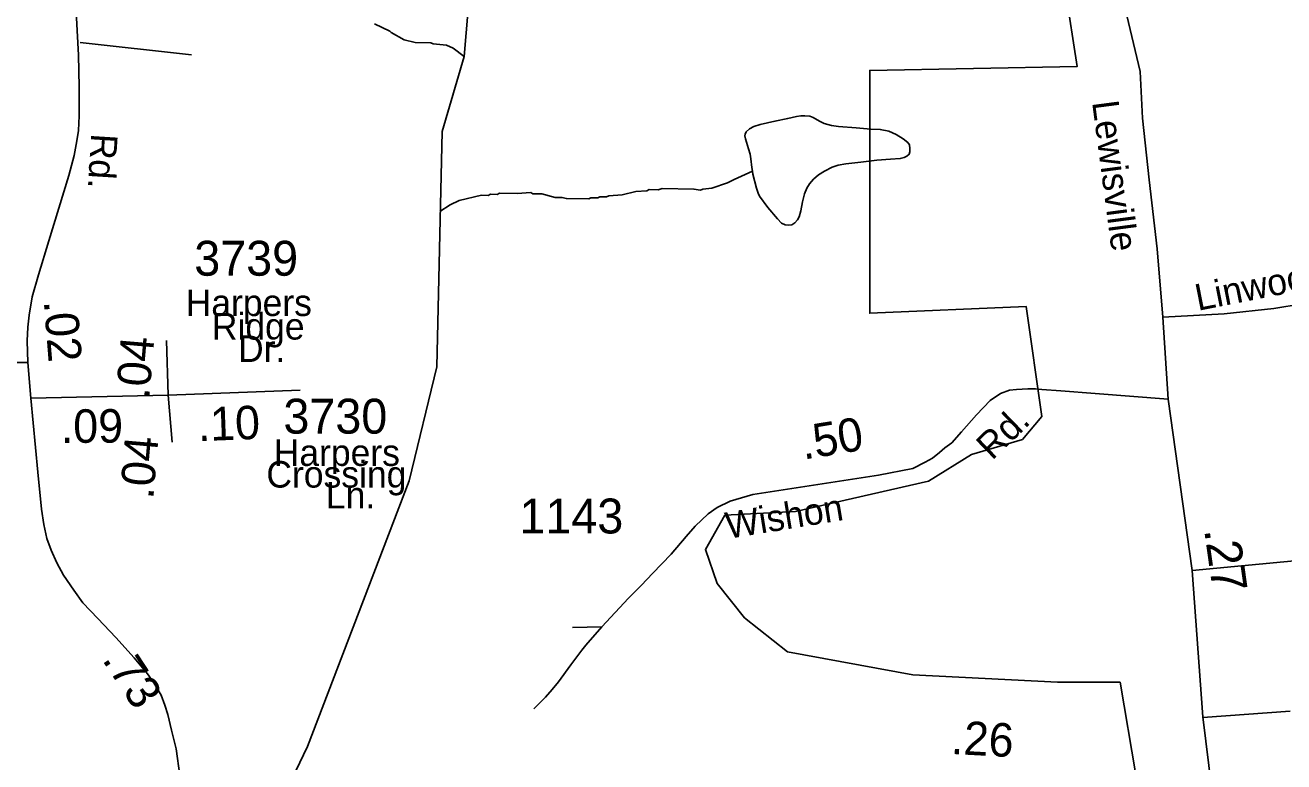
# Model space of a CAD drawing. Extents: x 1547597 to 1699558, y 810033 to 920809.
# Drawn here: x 1585386 to 1589892, y 839713 to 842351 of the extents above; entities that cross this region are included whole.
import ezdxf

# ---------------------------------------------------------------- set-up
doc = ezdxf.new("R2010")
doc.units = 0
for name, color, linetype in [('Exist Boundary Political City Limit New', 7, 'Continuous'), ('Exist Hydrographic Creek Single Shore', 7, 'Continuous'), ('Exist Hydrographic Misc Water Feature', 7, 'Continuous'), ('Exist Road Non-System Type 51', 7, 'Continuous'), ('Exist Road Non-System Type 51 Label', 7, 'Continuous'), ('Exist Road Secondary Mileage Hundredths English Label', 7, 'Continuous'), ('Exist Road Secondary Type 51 Attributed', 7, 'Continuous'), ('Exist Road Secondary Type 51 Label', 7, 'Continuous'), ('Exist Road Secondary Type 51 Number Label', 7, 'Continuous'), ('Map Preparation Boundary City Limit Buffer Line', 7, 'Continuous')]:
    doc.layers.add(name, color=color, linetype=linetype)

msp = doc.modelspace()

# ---------------------------------------------------------------- linework, layer by layer
at = {"layer": 'Exist Boundary Political City Limit New'}
msp.add_lwpolyline([(1589110.1, 842474), (1589152.2, 842202.2), (1588409.8, 842188.6), (1588409.8, 841318.7), (1588970.1, 841343), (1589026.1, 840948.8), (1588956.1, 840867.3), (1588774, 840812.9), (1588619.9, 840717.8), (1588143.6, 840609), (1587891.5, 840595.4), (1587821.5, 840473.1), (1587863.5, 840350.8), (1587961.5, 840228.5), (1588115.6, 840106.1), (1588563.9, 840024.6), (1589082.1, 839997.4), (1589306.2, 839997.4), (1589586.4, 838339.2)], dxfattribs=at)
at = {"layer": 'Exist Hydrographic Creek Single Shore'}
msp.add_lwpolyline([(1585117.5, 838293.2), (1585547.6, 838619.3), (1585792.5, 838867), (1585903.6, 839032.3), (1586217.5, 839393.6), (1586397.5, 839767.4), (1586761.5, 840718.6), (1586859.5, 841126.9), (1586879.5, 841970.2), (1586957.5, 842238.7), (1586986.8, 842579.1), (1586985.5, 842926.6), (1587021.2, 843660.8), (1587109.6, 843958.2), (1587214.6, 844349.9), (1587369.6, 844655.4), (1587407.5, 844969.8), (1587404.6, 845370.3), (1587343.5, 845755.6), (1587421.6, 845980.6), (1587450.6, 846262.3), (1587508.6, 847345.1)], dxfattribs=at)
at = {"layer": 'Exist Hydrographic Misc Water Feature'}
for points in [[(1586636.7, 842355.1), (1586691.2, 842329.2), (1586696.1, 842323.8), (1586742.7, 842298.5), (1586782.6, 842288.1), (1586838.6, 842287.4), (1586846.6, 842283.3), (1586894.5, 842278.7), (1586918.4, 842268.3), (1586957.5, 842238.7)], [(1587990, 841828.2), (1587988.3, 841840.7), (1587984.6, 841871.7), (1587981.4, 841888.4), (1587975.2, 841908.1), (1587965.1, 841943.4), (1587962.9, 841954.2), (1587963.6, 841960.7), (1587967.9, 841968.3), (1587978.8, 841978.8), (1587994.4, 841988), (1588017.1, 841994.8), (1588070.3, 842006.3), (1588116.2, 842016.8), (1588147.3, 842023.3), (1588162.7, 842025.4), (1588177.6, 842025.8), (1588195.4, 842024.8), (1588207.8, 842019.9), (1588229.6, 842006.4), (1588246.7, 841999), (1588273.4, 841991.3), (1588298.2, 841987.3), (1588361.7, 841982.6), (1588413.4, 841978.7), (1588447.2, 841977.5), (1588478.1, 841971), (1588504.7, 841959.2), (1588529.4, 841943.3), (1588545.8, 841929.9), (1588551.6, 841921.5), (1588553.8, 841908.4), (1588553.6, 841897.1), (1588550.4, 841888.2), (1588543.1, 841881.2), (1588533.6, 841876.6), (1588519.2, 841872.8), (1588484.7, 841870.4), (1588435.2, 841867.7), (1588377.5, 841859.8), (1588323.9, 841853.7), (1588297, 841849.4), (1588274.9, 841841.5), (1588247.9, 841828.3), (1588226.3, 841815), (1588208.8, 841799.3), (1588194.2, 841782.9), (1588185, 841766.4), (1588176.4, 841746.4), (1588169.3, 841717.4), (1588162.8, 841686), (1588157.1, 841664.7), (1588150.9, 841652.9), (1588141.3, 841642.4), (1588131.1, 841636), (1588119.2, 841634.4), (1588107.3, 841635.9), (1588093.6, 841641.5), (1588079.1, 841656.6), (1588044.7, 841697.6), (1588015.1, 841738.6), (1588009.9, 841748.8), (1588004.2, 841766.7), (1587991.4, 841817.5), (1587990, 841828.2)], [(1587990, 841828.2), (1587924.6, 841797.9), (1587900.5, 841786.2), (1587844.2, 841766.9), (1587812.2, 841763.4), (1587804.1, 841759.5), (1587780.2, 841763.8), (1587666.2, 841765.2), (1587652.2, 841761.4), (1587620.2, 841761.8), (1587612.2, 841757.9), (1587572.1, 841754.4), (1587524, 841743), (1587476, 841739.6), (1587467.9, 841735.7), (1587443.9, 841736), (1587435.9, 841732.1), (1587411.9, 841732.4), (1587403.8, 841728.5), (1587323.9, 841729.5), (1587308, 841733.7), (1587284, 841734), (1587236.1, 841746.6), (1587204.1, 841747), (1587196.2, 841751.1), (1587148.1, 841747.7), (1587084.2, 841748.5), (1587076.2, 841744.6), (1587052.2, 841744.9), (1587044.1, 841741), (1587020.1, 841741.3), (1586939.9, 841722.3), (1586907.7, 841706.8), (1586870.6, 841682.9)]]:
    msp.add_lwpolyline(points, dxfattribs=at)
at = {"layer": 'Exist Road Non-System Type 51'}
for p, q in [((1585583.7, 842288), (1585981.2, 842244.1)), ((1587450.4, 840195.6), (1587346.3, 840193.5)), ((1589915.1, 839894.1), (1589602.3, 839871))]:
    msp.add_line(p, q, dxfattribs=at)
for points in [[(1589459.1, 841304.4), (1589678.8, 841317.3), (1589855.9, 841335.7), (1589957.4, 841352.3), (1590075.6, 841396.6), (1590375.5, 841533.2), (1590454.8, 841566.4), (1590488.1, 841575.7), (1590548, 841581.2), (1590599.7, 841579.3), (1590704, 841568.3)], [(1589564.2, 840397.5), (1589980.9, 840437.5), (1590067, 840438.2), (1590134.9, 840435.2), (1590188.9, 840434.5), (1590221, 840435.8), (1590277.2, 840443.1), (1590301.3, 840450.8), (1590337.5, 840468.3), (1590353.8, 840480), (1590372.1, 840495.8)], [(1587295.6, 839998.9), (1587273.5, 839971.3), (1587248.9, 839944.3), (1587207.1, 839902.5)]]:
    msp.add_lwpolyline(points, dxfattribs=at)
at = {"layer": 'Exist Road Secondary Type 51 Attributed'}
for points in [[(1589477.6, 841011.9), (1589459.1, 841304.4), (1589438.8, 841549.8), (1589409.6, 841796.2), (1589386.2, 842017.1), (1589377.6, 842185.1), (1589329.6, 842385.6), (1589301.1, 842561.6), (1589283.2, 842699.3), (1589280.7, 842795.5), (1589287.7, 842850.7), (1589283, 842943.2), (1589280.1, 843015.3), (1589281.4, 843141.5), (1589298.4, 843316.5), (1589317.9, 843904.6), (1589327.5, 844094.6)], [(1585566.5, 842443.3), (1585576.8, 842243.4), (1585579.2, 842130.2), (1585579.5, 842025.8), (1585577.7, 841973.9), (1585571.2, 841936.7), (1585561.2, 841883.7), (1585543.2, 841811.7), (1585470.9, 841578.8), (1585433.8, 841456.7), (1585411.4, 841377.7), (1585400.2, 841312.2), (1585395.5, 841269.1), (1585393.7, 841220.2), (1585395.8, 841142.3)], [(1585892.2, 841221.2), (1585898.1, 841026.1)], [(1585352.1, 841142.3), (1585395.8, 841142.3)], [(1585395.8, 841142.3), (1585407, 841014.4)], [(1585407, 841014.4), (1585898.1, 841026.1)], [(1585898.1, 841026.1), (1586370.8, 841043.8)], [(1585898.1, 841026.1), (1585912.9, 840857.6)], [(1589477.6, 841011.9), (1589217.1, 841031.5), (1589094.3, 841041.4), (1589025.5, 841046.3), (1589003.4, 841048.7), (1588976.3, 841048.7), (1588934.6, 841046.3), (1588910, 841043.8), (1588878, 841031.5), (1588841.2, 841006.9), (1588792, 840955.3), (1588738, 840893.8), (1588703.6, 840854.5), (1588679, 840837.3), (1588659.3, 840820.1), (1588634.8, 840800.4), (1588607.7, 840785.6), (1588563.5, 840763.5), (1588440.6, 840738.9), (1587991, 840670.1), (1587909.9, 840645.5), (1587863.2, 840623.4), (1587831.3, 840601.2), (1587784.6, 840557), (1587752.6, 840520.1), (1587698.6, 840456.2), (1587632.2, 840387.3), (1587592.9, 840345.5), (1587546.2, 840298.8), (1587450.4, 840195.6), (1587393.2, 840130.7), (1587379.1, 840112), (1587339.8, 840060.3), (1587295.6, 839998.9)], [(1585407, 841014.4), (1585431.7, 840750.1), (1585444.4, 840618), (1585452.7, 840562.6), (1585463.3, 840512.5), (1585479.8, 840470.6), (1585499.3, 840425.2), (1585523.7, 840381), (1585560.9, 840327.9), (1585593.3, 840282.5), (1585647, 840226.4), (1585710.4, 840157.4), (1585777, 840084.9), (1585824.2, 840028.3), (1585846.6, 839995.8), (1585872.6, 839951.6), (1585886.1, 839915), (1585897.6, 839882.6), (1585910.6, 839826), (1585926.5, 839759.3), (1585939.5, 839663.8)], [(1589634.3, 839612.3), (1589602.1, 839874.3), (1589564.2, 840397.5), (1589477.6, 841011.9)]]:
    msp.add_lwpolyline(points, dxfattribs=at)
at = {"layer": 'Map Preparation Boundary City Limit Buffer Line'}
msp.add_lwpolyline([(1589110.1, 842474), (1589152.2, 842202.2), (1588409.8, 842188.6), (1588409.8, 841318.7), (1588970.1, 841343), (1589026.1, 840948.8), (1588956.1, 840867.3), (1588774, 840812.9), (1588619.9, 840717.8), (1588143.6, 840609), (1587891.5, 840595.4), (1587821.5, 840473.1), (1587863.5, 840350.8), (1587961.5, 840228.5), (1588115.6, 840106.1), (1588563.9, 840024.6), (1589082.1, 839997.4), (1589306.2, 839997.4), (1589586.4, 838339.2)], dxfattribs=at)

# ---------------------------------------------------------------- texts
at = {"layer": 'Exist Road Non-System Type 51 Label'}
msp.add_text('Linwood', height=95, rotation=11.1114, dxfattribs=at).set_placement((1589584.6, 841327.4))
at = {"layer": 'Exist Road Secondary Mileage Hundredths English Label'}
for s, height, rotation, p in [('.02', 120, 274.6225, (1585452.7, 841362.4)), ('.04', 120, 85.1325, (1585830.1, 841008.5)), ('.09', 120, 0.3495, (1585514.1, 840854.5)), ('.10', 120, 2.1494, (1586006, 840860.8)), ('.50', 120, 9.2698, (1588172.8, 840794.7)), ('.04', 120, 85.1324, (1585844.7, 840651)), ('.27', 125, 278.026, (1589606.7, 840543.5)), ('.73', 120, 303.2455, (1585659.8, 840078.9)), ('.26', 120, 356.9385, (1588699.1, 839741.1))]:
    msp.add_text(s, height=height, rotation=rotation, dxfattribs=at).set_placement(p)
at = {"layer": 'Exist Road Secondary Type 51 Label'}
for s, rotation, p in [('Lewisville', 277.4723, (1589205.7, 842075)), ('Rd.', 266.4437, (1585623, 841964.1)), ('Rd.', 44.1267, (1588847.9, 840789.8)), ('Wishon', 9.2698, (1587902, 840510.8))]:
    msp.add_text(s, height=95, rotation=rotation, dxfattribs=at).set_placement(p)
for s, p in [('Harpers', (1585960.9, 841309)), ('Ridge', (1586054.6, 841224.7)), ('Dr.', (1586148.3, 841144.4)), ('Harpers', (1586276.1, 840772.2)), ('Crossing', (1586249.8, 840694.7)), ('Ln.', (1586462.8, 840619.9))]:
    msp.add_text(s, height=95, dxfattribs=at).set_placement(p)
at = {"layer": 'Exist Road Secondary Type 51 Number Label'}
for s, p in [('3739', (1585991.6, 841453.4)), ('3730', (1586310.8, 840887.9)), ('1143', (1587155.7, 840530.4))]:
    msp.add_text(s, height=125, dxfattribs=at).set_placement(p)

doc.saveas('drawing.dxf')
